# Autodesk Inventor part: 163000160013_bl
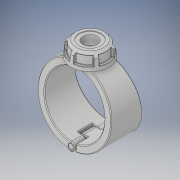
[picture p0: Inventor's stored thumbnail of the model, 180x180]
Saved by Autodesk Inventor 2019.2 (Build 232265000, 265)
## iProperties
Created: 2022-02
Part Number: 163000160013_bl
Material: Generic
Description: Plassadle Threaded 160x1 1/4''
Document SubType Name: Modeling
Designer: comp2
Density: 1 g/cm^3
Appearance: Default
Author: comp2
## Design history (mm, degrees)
derived "16300.ipt"
feature "Solid1::16300.ipt" dims "ScaleForDerivedMember" = 10
feature "Solid2::16300.ipt" dims "ScaleForDerivedMember" = 10
feature "Solid3::16300.ipt" dims "ScaleForDerivedMember" = 10
feature "Solid4::16300.ipt" dims "ScaleForDerivedMember" = 10
tag "TaggingFeature1"
body "Solid1"
body "Solid2"
body "Solid3"
body "Solid4"
other parameters: "d2" = 197 [user parameter], "d7" = 187.15 [user parameter], "d8" = 85 deg [user parameter], "d9" = 45 deg [user parameter], "d10" = 102 [user parameter], "d11" = 49 [user parameter], "d12" = 27.2895 [user parameter], "d13" = 42.84 [user parameter], "d14" = 58.428 [user parameter], "d42" = 3.7 [user parameter], "d49" = 3.94 [user parameter], "d50" = 106 [user parameter], "d51" = 0 [user parameter], "d52" = 25.9 [user parameter], "d53" = 108.35 [user parameter], "d54" = 37.1 [user parameter], "d55" = 0 [user parameter], "d56" = 21.2 [user parameter], "d57" = 21.2 [user parameter], "d59" = 0 [user parameter], "d60" = 106 [user parameter], "d61" = 0 [user parameter], "d62" = 37.1 [user parameter], "d63" = 0 [user parameter], "d65" = 0 [user parameter], "d67" = 0 [user parameter], "d69" = 0 [user parameter], "d70" = 1 [user parameter], "d71" = 101.76 [user parameter], "d72" = 0 [user parameter], "d73" = 2 [user parameter], "d78" = 86.7 [user parameter], "d79" = 5.1 [user parameter], "d80" = 60 deg [user parameter], "d81" = 5.1 [user parameter], "d84" = 0 [user parameter], "d85" = 1 [user parameter], "d87" = 360 deg [user parameter], "d122" = 58 [user parameter], "d124" = 42.80128 [user parameter], "d125" = 1.94925 [user parameter], "d127" = 235 [user parameter], "d129" = 38.952 [user parameter], "d130" = 33.1092 [user parameter], "d131" = 37.7 [user parameter], "d132" = 45 deg [user parameter], "d133" = 26.39 [user parameter], "d134" = 19.476 [user parameter], "d136" = 0 [user parameter], "d138" = 0 [user parameter], "d1" = 25 [user parameter], "B" = 197 [user parameter], "L" = 106 [user parameter], "E_" = 54 [user parameter], "E1" = 102 [user parameter], "H1" = 235 [user parameter], "H2" = 58 [user parameter], "H3" = 78 [user parameter], "H_costum" = 49 [user parameter], "Rp" = 38.952 [user parameter], "d128" = 38.985 [user parameter]
